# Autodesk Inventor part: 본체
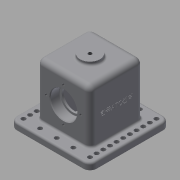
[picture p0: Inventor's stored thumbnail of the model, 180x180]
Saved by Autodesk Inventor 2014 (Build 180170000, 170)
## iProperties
Created: 2018-11
Part Number: 본체
Material: Generic
Document SubType Name: Modeling
Designer: kh
Density: 1 g/cm^3
Appearance: Default
Author: kh
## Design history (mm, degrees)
sketch "스케치1"
  geometry: L1 (-60, -60)-(60, -60); L2 (60, -60)-(60, 60); L3 (60, 60)-(-60, 60); L4 (-60, 60)-(-60, -60); L5 (-60, -60)-(60, 60); L6 (60, -60)-(-60, 60); 1 further point
  constraints: 12 end point, 2 midpoint, 2 parallel, 1 horizontal, 1 perpendicular
  dimensions: "d0" = 120 distance of L3.end L2.end; "d1" = 120 distance of L2.end L1.end
extrude "돌출1" new body sketch "스케치1" distance "d2" = 10; taper "d3" = 0 deg
sketch "스케치2"
  geometry: L1 (-40, -40)-(40, -40); L2 (40, -40)-(40, 40); L3 (40, 40)-(-40, 40); L4 (-40, 40)-(-40, -40); L5 (-40, -40)-(40, 40); L6 (40, -40)-(-40, 40); 1 further point
  constraints: 12 end point, 2 midpoint, 2 parallel, 1 horizontal, 1 perpendicular
  dimensions: "d4" = 80 distance of L3.end L2.end; "d5" = 80 distance of L2.end L1.end
extrude "돌출2" join sketch "스케치2" distance "d6" = 80; taper "d7" = 0 deg
sketch "스케치3"
  geometry: C1 r 15 at (0, 0); 1 further point
  constraints: 1 centre point, 1 coincident
  dimensions: "d8" = 15 radius of C1
extrude "돌출3" join sketch "스케치3" distance "d9" = 5; taper "d10" = 0 deg
sketch "스케치4"
  geometry: L1 (-23, -30)-(23, -30); L2 (23, -30)-(23, 30); L3 (23, 30)-(-23, 30); L4 (-23, 30)-(-23, -30); L5 (-23, -30)-(23, 30); L6 (23, -30)-(-23, 30); 1 further point
  constraints: 12 end point, 2 midpoint, 2 parallel, 1 horizontal, 1 perpendicular
  dimensions: "d11" = 46 distance of L3.end L2.end; "d12" = 60 distance of L2.end L1.end
extrude "돌출4" cut sketch "스케치4" distance "d13" = 80; taper "d14" = 0 deg
sketch "스케치5"
  geometry: L1 (-40, 10)-(-40, 90) reference; L2 (40, 10)-(40, 90) reference; L3 (-40, 68)-(-26, 68); L4 (-26, 68)-(-26, 64.5); L5 (-26, 64.5)-(26, 64.5); L6 (26, 64.5)-(26, 68); L7 (26, 68)-(40, 68); L8 (-40, 48)-(40, 48); L9 (-23, 0)-(-23, 80) reference; L10 (0, 0)-(0, 94.541); L11 (-40, 68)-(-40, 48); L12 (40, 68)-(40, 48)
  constraints: 18 end point, 4 point on line, 3 collinear, 3 perpendicular, 2 parallel, 1 horizontal, 2 other
  dimensions: "d15" = 48 distance from line of L10.start L8; "d16" = 33 diameter of L5 L8; "d17" = 40 diameter of L7 L8; "d18" = 14 distance of L3.start L3.end
revolve "회전1" sketch "스케치5" stored, may be unused: angle "d19" = 90 deg
sketch "스케치6" dims "d20" = 26
  geometry: L1 (-38, 40)-(-38, 66); C1 r 20 at (-38, 40) reference; 2 further points
  constraints: 2 coincident, 2 end point, 1 vertical, 1 vertical alignment, 2 other
hole "구멍1" sketch "스케치6" at (-38, 66) diameter "d21" = 3.459; stored, may be unused: countersink angle "d25" = 90 deg, drill point angle "d27" = 118 deg; dims "d22" = 8, "d23" = 4, "d24" = 2, "d26" = 10
hole "구멍2" diameter "d33" = 5.459; stored, may be unused: countersink angle "d37" = 90 deg, drill point angle "d39" = 118 deg; dims "d31" = 10, "d32" = 10, "d34" = 15, "d35" = 4, "d36" = 2, "d38" = 10
fillet "모깎기1" dims "d40" = 10
sketch "스케치7"
  geometry: A1 r 10 centre (-50, 50) between (-50, 60) and (-60, 50) reference; 2 further points
  constraints: 1 coincident
hole "구멍3" sketch "스케치7" at (-50, 50) diameter "d41" = 6.6; stored, may be unused: countersink angle "d45" = 90 deg, drill point angle "d47" = 118 deg; dims "d42" = 15, "d43" = 4, "d44" = 2, "d46" = 10
fillet "모깎기2" dims "d54" = 3
fillet "모깎기3" dims "d55" = 3
fillet "모깎기4" dims "d56" = 8
fillet "모깎기5" dims "d57" = 8
fillet "모깎기6" dims "d58" = 3
fillet "모깎기7" dims "d59" = 3
fillet "모깎기8" dims "d60" = 0.6
sketch "스케치8"
  geometry: L1 (74.887, -51.602)-(25.113, -51.602); L2 (25.113, -51.602)-(25.113, -44.398); L3 (25.113, -44.398)-(74.887, -44.398); L4 (74.887, -44.398)-(74.887, -51.602); L5 (74.887, -51.602)-(25.113, -44.398); L6 (25.113, -51.602)-(74.887, -44.398); L7 (50, 0)-(50, -93.783); L8 (100, 0)-(0, 0) reference; L9 (35, -95)-(65, -95) reference; 5 further points
  constraints: 6 end point, 5 midpoint, 5 point on line, 1 parallel, 2 other
  dimensions: "d61" = 48 distance of L7.start point (50, -48)
feature "엠보싱1" sketch "스케치8" dims "d0" = 120, "d1" = 120, "d62" = 0.5, "d63" = 0
chamfer "모따기1" distance "d64" = 1; stored, may be unused: second distance "d65" = 2, angle "d66" = 45 deg
fillet "모깎기9" dims "d67" = 3
node "솔리드1"
pattern_circular "원형 패턴1" dims angle "d29" = 360 deg
mirror "대칭1"
pattern_linear "직사각형 패턴1" dims "d50" = 10
mirror "대칭2"
pattern_linear "직사각형 패턴2" dims "d53" = 25
mirror "대칭3"
